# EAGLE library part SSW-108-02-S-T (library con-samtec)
THROUGH-HOLE .025" SQ POST SOCKET Source: Samtec SSW.pdf
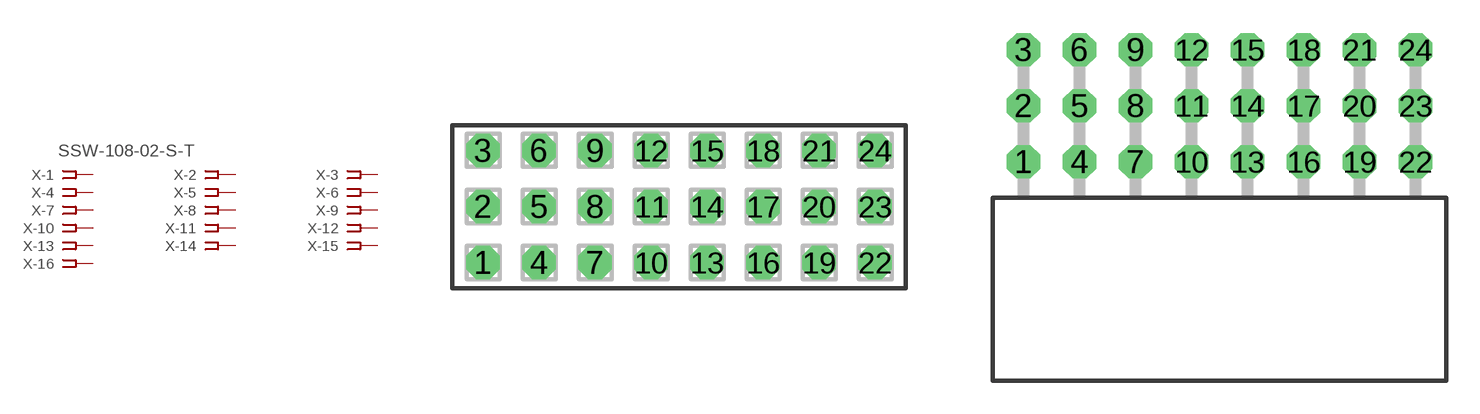
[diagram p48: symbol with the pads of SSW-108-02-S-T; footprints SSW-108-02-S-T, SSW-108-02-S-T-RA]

Designator prefix X; gates -1=FPINV -2=FPIN -3=FPIN -4=FPIN -5=FPIN -6=FPIN -7=FPIN -8=FPIN -9=FPIN -10=FPIN -11=FPIN -12=FPIN -13=FPIN -14=FPIN -15=FPIN -16=FPIN -17=FPIN -18=FPIN -19=FPIN -20=FPIN -21=FPIN -22=FPIN -23=FPIN -24=FPIN

## SSW-108-02-S-T (MPN: SSW-108-02-S-T; OC_FARNELL: unknown; OC_NEWARK: 82P4351)  [SSW-108-02-S-T]
1  -1:1  pas
2  -2:1  pas
3  -3:1  pas
4  -4:1  pas
5  -5:1  pas
6  -6:1  pas
7  -7:1  pas
8  -8:1  pas
9  -9:1  pas
10  -10:1  pas
11  -11:1  pas
12  -12:1  pas
13  -13:1  pas
14  -14:1  pas
15  -15:1  pas
16  -16:1  pas
17  -17:1  pas
18  -18:1  pas
19  -19:1  pas
20  -20:1  pas
21  -21:1  pas
22  -22:1  pas
23  -23:1  pas
24  -24:1  pas

## SSW-108-02-S-TRA (MPN: SSW-108-02-S-T-RA; OC_FARNELL: unknown; OC_NEWARK: 82P4352)  [SSW-108-02-S-T-RA]
Pads as for SSW-108-02-S-T

## Footprint SSW-108-02-S-T (pad centres in mm)
THROUGH-HOLE .025" SQ POST SOCKET Source: Samtec SSW.pdf
drill 1 pad 1.5 octagon: 1 -8.89,-2.54; 2 -8.89,0; 3 -8.89,2.54; 4 -6.35,-2.54; 5 -6.35,0; 6 -6.35,2.54; 7 -3.81,-2.54; 8 -3.81,0; 9 -3.81,2.54; 10 -1.27,-2.54; 11 -1.27,0; 12 -1.27,2.54; 13 1.27,-2.54; 14 1.27,0; 15 1.27,2.54; 16 3.81,-2.54; 17 3.81,0; 18 3.81,2.54; 19 6.35,-2.54; 20 6.35,0; 21 6.35,2.54; 22 8.89,-2.54; 23 8.89,0; 24 8.89,2.54

## Footprint SSW-108-02-S-T-RA (pad centres in mm)
THROUGH-HOLE .025" SQ POST SOCKET Source: Samtec SSW.pdf
drill 1 pad 1.5 octagon: 1 -8.89,1.524; 2 -8.89,4.064; 3 -8.89,6.604; 4 -6.35,1.524; 5 -6.35,4.064; 6 -6.35,6.604; 7 -3.81,1.524; 8 -3.81,4.064; 9 -3.81,6.604; 10 -1.27,1.524; 11 -1.27,4.064; 12 -1.27,6.604; 13 1.27,1.524; 14 1.27,4.064; 15 1.27,6.604; 16 3.81,1.524; 17 3.81,4.064; 18 3.81,6.604; 19 6.35,1.524; 20 6.35,4.064; 21 6.35,6.604; 22 8.89,1.524; 23 8.89,4.064; 24 8.89,6.604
